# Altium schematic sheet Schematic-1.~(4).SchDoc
size 381 x 241 mm; SheetNumber: 1; SheetTotal: 1
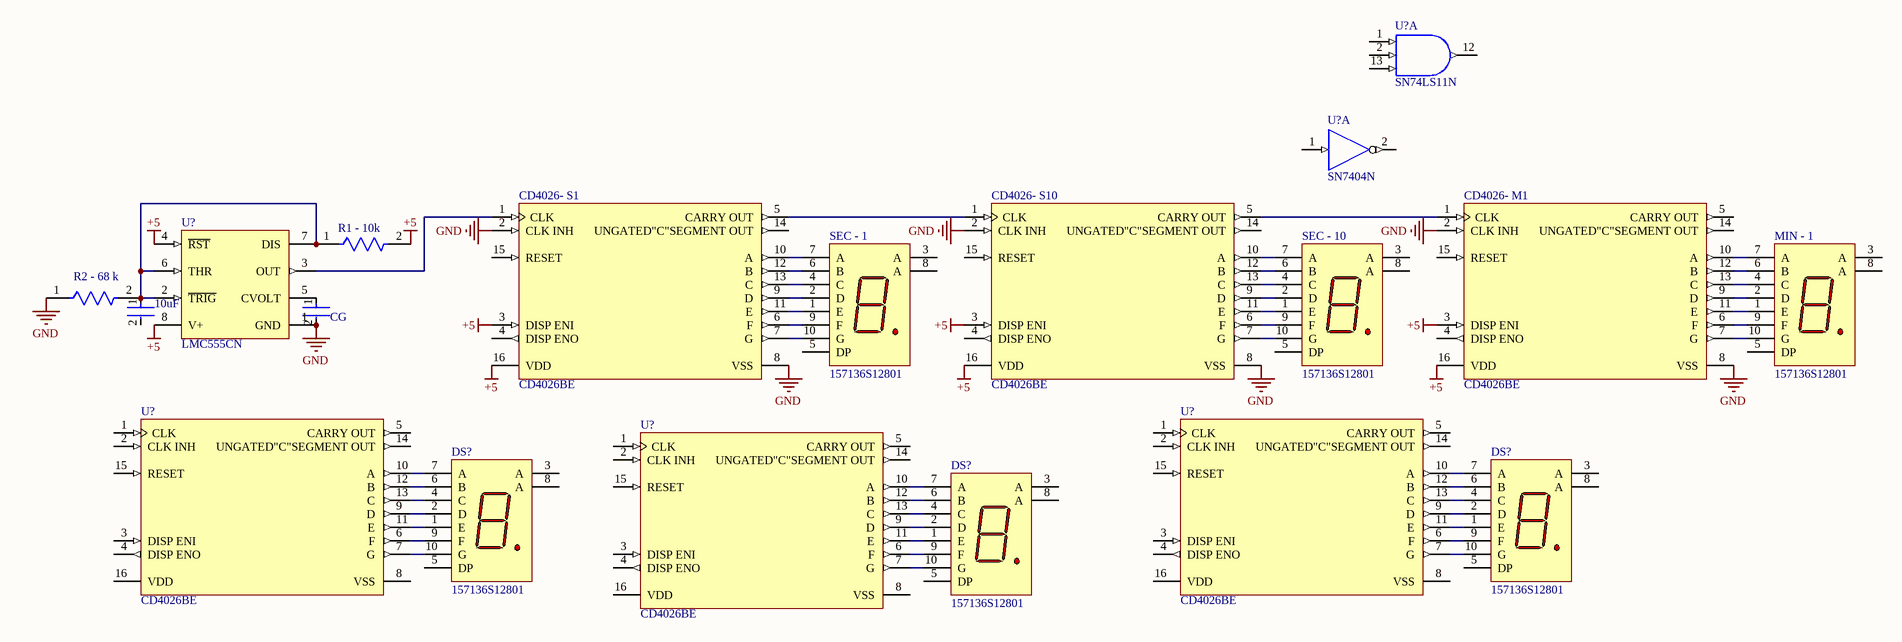
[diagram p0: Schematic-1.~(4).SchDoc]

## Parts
(Parts that share a designator on the sheet are numbered #1, #2 ... from top to bottom, then left to right.)
10uF  VY1472M63Y5UQ6TV0  [FP-VY1472M63Y5UQ6TV0-MFG]  (value not drawn)
CD4026-_M1  CD4026BE  [N0016A]
CD4026-_S1  CD4026BE  [N0016A]
CD4026-_S10  CD4026BE  [N0016A]
CG  VY1472M63Y5UQ6TV0  [FP-VY1472M63Y5UQ6TV0-MFG]  (value not drawn)
DS?#1  157136S12801  [WL-T7DS_L17.5W12.4H7]
DS?#2  157136S12801  [WL-T7DS_L17.5W12.4H7]
DS?#3  157136S12801  [WL-T7DS_L17.5W12.4H7]
MIN_-_1  157136S12801  [WL-T7DS_L17.5W12.4H7]
R1_-_10k  VR37000001204JA100  [FP-VR37-MFG]  (value not drawn)
R2_-_68_k  VR37000001204JA100  [FP-VR37-MFG]  (value not drawn)
SEC_-_1  157136S12801  [WL-T7DS_L17.5W12.4H7]
SEC_-_10  157136S12801  [WL-T7DS_L17.5W12.4H7]
U?#1  SN74LS11N  [N0014A]  (part A of 4)
U?#2  SN7404N  [N0014A]  (part A of 7)
U?#3  LMC555CN  [P0008A]
U?#4  CD4026BE  [N0016A]
U?#5  CD4026BE  [N0016A]
U?#6  CD4026BE  [N0016A]

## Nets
+5: CD4026-_M1.3(DISP_ENI) CD4026-_M1.16(VDD) CD4026-_S1.3(DISP_ENI) CD4026-_S1.16(VDD) CD4026-_S10.3(DISP_ENI) CD4026-_S10.16(VDD) R1_-_10k.2 U?#3.4(~{RST}) U?#3.8(V+)
GND: CD4026-_M1.2(CLK_INH) CD4026-_M1.8(VSS) CD4026-_S1.2(CLK_INH) CD4026-_S1.8(VSS) CD4026-_S10.2(CLK_INH) CD4026-_S10.8(VSS) CG.2 R2_-_68_k.1 U?#3.1(GND)
Net10uF_1: 10uF.1 R1_-_10k.1 R2_-_68_k.2 U?#3.2(~{TRIG}) U?#3.6(THR) U?#3.7(DIS)
NetCD4026-_M1_1: CD4026-_M1.1(CLK) CD4026-_S10.5(CARRY_OUT)
NetCD4026-_M1_6: CD4026-_M1.6(F) MIN_-_1.9(F)
NetCD4026-_M1_7: CD4026-_M1.7(G) MIN_-_1.10(G)
NetCD4026-_M1_9: CD4026-_M1.9(D) MIN_-_1.2(D)
NetCD4026-_M1_10: CD4026-_M1.10(A) MIN_-_1.7(A)
NetCD4026-_M1_11: CD4026-_M1.11(E) MIN_-_1.1(E)
NetCD4026-_M1_12: CD4026-_M1.12(B) MIN_-_1.6(B)
NetCD4026-_M1_13: CD4026-_M1.13(C) MIN_-_1.4(C)
NetCD4026-_S1_1: CD4026-_S1.1(CLK) U?#3.3(OUT)
NetCD4026-_S1_5: CD4026-_S1.5(CARRY_OUT) CD4026-_S10.1(CLK)
NetCD4026-_S1_6: CD4026-_S1.6(F) SEC_-_1.9(F)
NetCD4026-_S1_7: CD4026-_S1.7(G) SEC_-_1.10(G)
NetCD4026-_S1_9: CD4026-_S1.9(D) SEC_-_1.2(D)
NetCD4026-_S1_10: CD4026-_S1.10(A) SEC_-_1.7(A)
NetCD4026-_S1_11: CD4026-_S1.11(E) SEC_-_1.1(E)
NetCD4026-_S1_12: CD4026-_S1.12(B) SEC_-_1.6(B)
NetCD4026-_S1_13: CD4026-_S1.13(C) SEC_-_1.4(C)
NetCD4026-_S10_6: CD4026-_S10.6(F) SEC_-_10.9(F)
NetCD4026-_S10_7: CD4026-_S10.7(G) SEC_-_10.10(G)
NetCD4026-_S10_9: CD4026-_S10.9(D) SEC_-_10.2(D)
NetCD4026-_S10_10: CD4026-_S10.10(A) SEC_-_10.7(A)
NetCD4026-_S10_11: CD4026-_S10.11(E) SEC_-_10.1(E)
NetCD4026-_S10_12: CD4026-_S10.12(B) SEC_-_10.6(B)
NetCD4026-_S10_13: CD4026-_S10.13(C) SEC_-_10.4(C)
NetCG_1: CG.1 U?#3.5(CVOLT)
NetDS?#1_1: DS?#1.1(E) U?#4.11(E)
NetDS?#1_2: DS?#1.2(D) U?#4.9(D)
NetDS?#1_4: DS?#1.4(C) U?#4.13(C)
NetDS?#1_6: DS?#1.6(B) U?#4.12(B)
NetDS?#1_7: DS?#1.7(A) U?#4.10(A)
NetDS?#1_9: DS?#1.9(F) U?#4.6(F)
NetDS?#1_10: DS?#1.10(G) U?#4.7(G)
NetDS?#2_1: DS?#2.1(E) U?#5.11(E)
NetDS?#2_2: DS?#2.2(D) U?#5.9(D)
NetDS?#2_4: DS?#2.4(C) U?#5.13(C)
NetDS?#2_6: DS?#2.6(B) U?#5.12(B)
NetDS?#2_7: DS?#2.7(A) U?#5.10(A)
NetDS?#2_9: DS?#2.9(F) U?#5.6(F)
NetDS?#2_10: DS?#2.10(G) U?#5.7(G)
NetDS?#3_1: DS?#3.1(E) U?#6.11(E)
NetDS?#3_2: DS?#3.2(D) U?#6.9(D)
NetDS?#3_4: DS?#3.4(C) U?#6.13(C)
NetDS?#3_6: DS?#3.6(B) U?#6.12(B)
NetDS?#3_7: DS?#3.7(A) U?#6.10(A)
NetDS?#3_9: DS?#3.9(F) U?#6.6(F)
NetDS?#3_10: DS?#3.10(G) U?#6.7(G)

Not connected (* = marked no-connect by the designer): 10uF 2; CD4026-_M1 4(DISP_ENO) 5(CARRY_OUT) 14(UNGATED"C"SEGMENT_OUT) 15(RESET); CD4026-_S1 4(DISP_ENO) 14(UNGATED"C"SEGMENT_OUT) 15(RESET); CD4026-_S10 4(DISP_ENO) 14(UNGATED"C"SEGMENT_OUT) 15(RESET); DS?#1 3(A) 5(DP) 8(A); DS?#2 3(A) 5(DP) 8(A); DS?#3 3(A) 5(DP) 8(A); MIN_-_1 3(A) 5(DP) 8(A); SEC_-_1 3(A) 5(DP) 8(A); SEC_-_10 3(A) 5(DP) 8(A); U?#1 1(1A) 2(1B) 12(1Y) 13(1C); U?#2 1(1A) 2(~{1Y}); U?#4 1(CLK) 2(CLK_INH) 3(DISP_ENI) 4(DISP_ENO) 5(CARRY_OUT) 8(VSS) 14(UNGATED"C"SEGMENT_OUT) 15(RESET) 16(VDD); U?#5 1(CLK) 2(CLK_INH) 3(DISP_ENI) 4(DISP_ENO) 5(CARRY_OUT) 8(VSS) 14(UNGATED"C"SEGMENT_OUT) 15(RESET) 16(VDD); U?#6 1(CLK) 2(CLK_INH) 3(DISP_ENI) 4(DISP_ENO) 5(CARRY_OUT) 8(VSS) 14(UNGATED"C"SEGMENT_OUT) 15(RESET) 16(VDD)

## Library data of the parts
10uF CG = CMP-02417-000050-1: CAP CER 4700PF 760VAC Y5U RADIAL; Voltage Rating (AC): 500V; Lead Diameter: 0.6mm; Capacitance: 4.7nF; Tolerance: 20%; Lead/Base Style: Kinked
CD4026-_M1 CD4026-_S1 CD4026-_S10 U?#4-U?#6 = CMP-1623-00561-2: CMOS Decade Counter/Divider with Decoded 7-Segment Display Outputs and Display Enable, N0016A, TUBE; Manufacturer: Texas Instruments; ICC @ Nom Voltage(Max)(mA): 0.03; tpd @ Nom Voltage(Max)(ns): 250; F @ Nom Voltage(Max)(Mhz): 8; Bits(#): 7; VCC(Max)(V): 18; VCC(Min)(V): 3; Output Drive (IOL/IOH)(Max)(mA): 1.5/-1.5; Inputs: 1; Rating: Catalog; Technology Family: CD4000; Schmitt Trigger: No; Voltage(Nom)(V): 5,10,15
DS?#1-DS?#3 MIN_-_1 SEC_-_1 SEC_-_10 = CMP-03913-119893999-3: 7-Seg Display, Comm Anode, Super Red Rohs Compliant: Yes; Forward Voltage: 2V; Dominant Wavelength: 635nm; Max Reverse Voltage (DC): 5V; Forward Current: 100mA; Luminous Intensity: 20mcd
R1_-_10k R2_-_68_k = CMP-02408-000054-1: RES 1.2M OHM 5% 1/2W AXIAL; Voltage Rating: 3.5kV; Power Rating: 500mW; Temperature Coefficient: 200ppm/°C; Resistance: 1.2MR
U?#1 = CMP-0777-00254-3: Triple 3-input positive-AND gates, N0014A, TUBE; Manufacturer: Texas Instruments; Output Type: TTL; VCC(Min)(V): 4.75; Technology Family: LS; Bits(#): 3; Voltage(Nom)(V): 5; ICC @ Nom Voltage(Max)(mA): 0.0036; Rating: Catalog; VCC(Max)(V): 5.25; tpd @ Nom Voltage(Max)(ns): 15; Output Drive (IOL/IOH)(Max)(mA): 0/8; F @ Nom Voltage(Max)(Mhz): 35; Schmitt Trigger: No
U?#2 = CMP-1615-00872-2: Hex inverters, N0014A, TUBE; Generic Part Number: SN7404; Manufacturer: Texas Instruments; Voltage(Nom)(V): 5; Bits(#): 6; tpd @ Nom Voltage(Max)(ns): 22; Schmitt Trigger: No; VCC(Max)(V): 5.25; ICC @ Nom Voltage(Max)(mA): 0.033; Technology Family: TTL; Rating: Catalog; F @ Nom Voltage(Max)(Mhz): 35; Output Type: CMOS; VCC(Min)(V): 4.75; Output Drive (IOL/IOH)(Max)(mA): -0.4/16
U?#3 = CMP-0056-00035-3: CMOS Timer, 8-pin MDIP; Manufacturer: Texas Instruments; PowerWise: N; CompType: Analog IC; PackageTopMarking: NSUZXYTTE#*LMC*555CN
